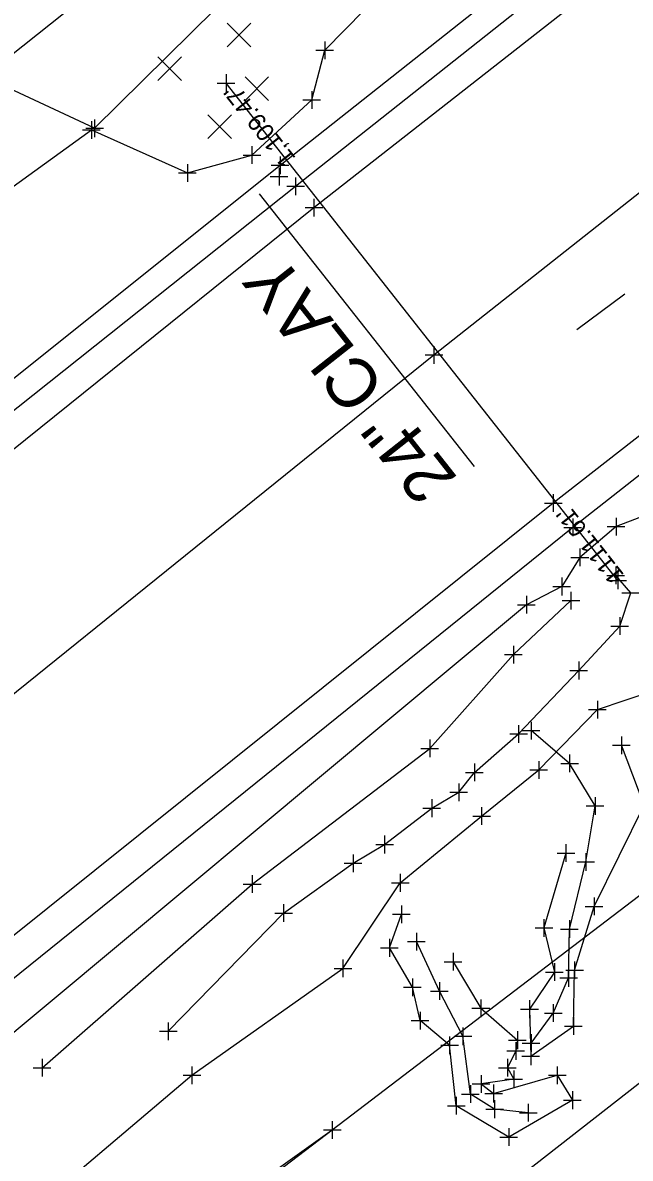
# Model space of a CAD drawing. Extents: x 2184635 to 2185378, y 369880 to 370486.
# Drawn here: x 2184841 to 2184875.3, y 370026.6 to 370090.6 of the extents above; entities that cross this region are included whole.
import ezdxf

# ---------------------------------------------------------------- set-up
doc = ezdxf.new("R2010")
doc.units = 0
for name, color, linetype in [('_CIVIL_CONSTRUCTION', 7, 'Continuous'), ('DR_X_Ditch', 7, 'Continuous'), ('DR_X_Storm_Sewer', 7, 'Continuous'), ('DR_X_Text', 7, 'Continuous'), ('GE_X_Alignment_100_Distances', 7, 'Continuous'), ('PM_X_CL_Pass_Proh_Lt', 7, 'Continuous'), ('PM_X_CL_Pass_Proh_Rt', 7, 'Continuous'), ('PM_X_Edge_Line', 7, 'Continuous'), ('PV_X_COP', 7, 'Continuous'), ('PV_X_EOP', 7, 'Continuous'), ('PV_X_Shoulder', 7, 'Continuous'), ('RD_X_Fence', 7, 'Continuous'), ('RW_X_CL', 7, 'Continuous'), ('RW_X_CL_100_Bearings', 7, 'Continuous'), ('SC_Scratch1', 7, 'Continuous'), ('SV_X_Break_Lines', 7, 'Continuous'), ('SV_X_Text', 7, 'Continuous'), ('SV_X_Top_of_Bank', 7, 'Continuous'), ('UT_X_Gas', 7, 'Continuous'), ('VG_X_Tree_Line_Lt', 7, 'Continuous')]:
    doc.layers.add(name, color=color, linetype=linetype)

msp = doc.modelspace()

# ---------------------------------------------------------------- linework, layer by layer
at = {"layer": '_CIVIL_CONSTRUCTION'}
for p, q in [((2184852.568, 370089.273), (2184853.901, 370090.608)), ((2184852.568, 370090.608), (2184853.901, 370089.273)), ((2184848.65, 370087.369), (2184849.984, 370088.704)), ((2184848.65, 370088.704), (2184849.984, 370087.369)), ((2184853.572, 370086.241), (2184854.905, 370087.576)), ((2184853.572, 370087.576), (2184854.905, 370086.241)), ((2184851.471, 370084.097), (2184852.805, 370085.432)), ((2184851.471, 370085.432), (2184852.805, 370084.097))]:
    msp.add_line(p, q, dxfattribs=at)
at = {"layer": 'DR_X_Ditch'}
msp.add_lwpolyline([(2184849.239, 370033.73), (2184855.751, 370040.4), (2184859.676, 370043.207), (2184861.454, 370044.268), (2184864.118, 370046.317), (2184865.643, 370047.216), (2184866.527, 370048.333), (2184869.021, 370050.508), (2184872.418, 370054.082), (2184874.729, 370056.587), (2184875.359, 370058.466), (2184874.504, 370059.447)], dxfattribs=at)
at = {"layer": 'DR_X_Storm_Sewer'}
msp.add_line((2184874.622, 370059.168), (2184852.499, 370087.222), dxfattribs=at)
at = {"layer": 'DR_X_Text'}
msp.add_line((2184854.367, 370080.977), (2184866.508, 370065.582), dxfattribs=at)
at = {"layer": 'GE_X_Alignment_100_Distances'}
for points in [[(2185264.317, 370371.308), (2185225.669, 370339.838), (2185186.917, 370307.744), (2185148.745, 370277.089), (2185109.073, 370245.724), (2185070.468, 370214.753), (2185031.044, 370183.419), (2184991.951, 370153.137), (2184952.243, 370122.384), (2184912.885, 370091.687), (2184876.597, 370062.99), (2184874.528, 370062.204), (2184872.479, 370060.466), (2184871.454, 370058.823), (2184869.46, 370057.791), (2184834.83, 370028.947), (2184796.151, 369998.173), (2184773.728, 369979.618), (2184757.686, 369965.832), (2184717.275, 369935.855), (2184678.357, 369904.181)], [(2184659.612, 369925.949), (2184700.373, 369957.788), (2184738.497, 369988.629), (2184777.827, 370020.252), (2184816.427, 370051.346), (2184855.546, 370082.582), (2184897.005, 370115.363), (2184935.605, 370145.229), (2184944.916, 370153.839), (2184957.869, 370164.566), (2184961.936, 370169.284), (2184974.725, 370179.722), (2184983.893, 370187.218), (2184992.505, 370194.662), (2184997.566, 370200.246)]]:
    msp.add_lwpolyline(points, dxfattribs=at)
at = {"layer": 'PM_X_CL_Pass_Proh_Lt'}
msp.add_lwpolyline([(2185262.142, 370374.202), (2185223.699, 370342.03), (2185185.178, 370310.659), (2185146.677, 370279.544), (2185107.738, 370248.35), (2185068.5, 370216.963), (2185029.051, 370186.04), (2184989.472, 370156.275), (2184949.89, 370125.369), (2184910.765, 370094.563), (2184870.979, 370063.529), (2184832.077, 370032.401), (2184793.204, 370001.486), (2184754.34, 369970.024), (2184715.121, 369938.505), (2184676.144, 369907.221)], dxfattribs=at)
at = {"layer": 'PM_X_CL_Pass_Proh_Rt'}
msp.add_lwpolyline([(2184772.075, 369998.33), (2184786.357, 370009.443), (2184824.962, 370040.257), (2184864.241, 370071.885), (2184905.968, 370104.805), (2184943.399, 370133.995), (2184983.483, 370165.213), (2185020.257, 370194.467), (2185061.224, 370226.635), (2185099.743, 370257.779), (2185139.182, 370289.511), (2185177.352, 370320.307), (2185216.054, 370351.804), (2185254.728, 370383.452)], dxfattribs=at)
at = {"layer": 'PM_X_Edge_Line'}
msp.add_lwpolyline([(2184661.525, 369922.948), (2184702.122, 369955.424), (2184740.459, 369986.306), (2184779.792, 370018.036), (2184818.421, 370048.832), (2184857.458, 370080.192), (2184899.139, 370112.801), (2184937.357, 370142.735), (2184976.78, 370173.64), (2185013.226, 370203.926), (2185054.743, 370235.213), (2185093.131, 370266.204), (2185132.902, 370298.208), (2185170.876, 370328.987), (2185209.713, 370360.437), (2185248.243, 370392.049)], dxfattribs=at)
at = {"layer": 'PV_X_COP'}
msp.add_lwpolyline([(2184667.936, 369914.544), (2184708.437, 369946.755), (2184746.444, 369977.522), (2184786.357, 370009.443), (2184824.962, 370040.257), (2184864.241, 370071.885), (2184905.968, 370104.805), (2184943.399, 370133.995), (2184983.483, 370165.213), (2185020.257, 370194.467), (2185061.224, 370226.635), (2185099.743, 370257.779), (2185139.182, 370289.511), (2185177.352, 370320.307), (2185216.054, 370351.804), (2185254.679, 370383.196)], dxfattribs=at)
at = {"layer": 'PV_X_EOP'}
for points in [[(2184661.562, 369922.858), (2184702.122, 369955.424), (2184740.459, 369986.306), (2184779.792, 370018.036), (2184818.421, 370048.832), (2184857.458, 370080.192), (2184899.139, 370112.801), (2184937.357, 370142.735), (2184976.78, 370173.64), (2185013.226, 370203.926), (2185054.743, 370235.213), (2185093.131, 370266.204), (2185132.902, 370298.208), (2185170.876, 370328.987), (2185209.713, 370360.437), (2185248.181, 370392.045)], [(2185262.152, 370374.256), (2185223.699, 370342.03), (2185185.178, 370310.659), (2185146.677, 370279.544), (2185107.738, 370248.35), (2185068.5, 370216.963), (2185029.051, 370186.04), (2184989.472, 370156.275), (2184949.89, 370125.369), (2184910.765, 370094.563), (2184870.979, 370063.529), (2184832.077, 370032.401), (2184793.204, 370001.486), (2184754.34, 369970.024), (2184715.121, 369938.505), (2184676.223, 369907.131)]]:
    msp.add_lwpolyline(points, dxfattribs=at)
at = {"layer": 'PV_X_Shoulder'}
for points in [[(2184660.616, 369924.653), (2184701.177, 369956.993), (2184739.308, 369987.689), (2184778.66, 370019.08), (2184817.145, 370050.202), (2184856.424, 370081.402), (2184897.962, 370114.276), (2184936.317, 370143.726), (2184975.811, 370174.815), (2184986.608, 370184.308), (2184994.082, 370192.548), (2185011.043, 370206.648), (2185033.171, 370224.287), (2185051.814, 370238.9), (2185062.885, 370246.964), (2185064.956, 370248.001), (2185067.328, 370248.113), (2185092.06, 370267.243), (2185132.002, 370299.513), (2185169.971, 370330.255), (2185208.837, 370361.607), (2185247.242, 370392.983)], [(2185263.127, 370373.08), (2185224.626, 370341.08), (2185185.979, 370309.587), (2185147.251, 370278.484), (2185108.316, 370247.412), (2185069.303, 370216.141), (2185029.865, 370185.151), (2184990.36, 370154.899), (2184951.083, 370123.826), (2184911.784, 370093.315), (2184872.077, 370062.156), (2184833.336, 370030.958), (2184794.18, 369999.967), (2184755.603, 369968.652), (2184716.02, 369937.324), (2184677.487, 369905.633)]]:
    msp.add_lwpolyline(points, dxfattribs=at)
at = {"layer": 'RD_X_Fence'}
for points in [[(2184709.157, 369984.536), (2184726.864, 369998.781), (2184769.898, 370032.731), (2184797.39, 370054.67), (2184814.475, 370067.872), (2184833.193, 370083.116), (2184887.166, 370125.991), (2184905.933, 370138.502)], [(2184782.754, 369936.252), (2184778.788, 369962.291), (2184805.018, 369984.824), (2184835.149, 370010.167), (2184846.096, 370019.315), (2184858.499, 370028.169), (2184882.065, 370046.135), (2184902.067, 370060.364), (2184933.298, 370086.709), (2184952.934, 370104.808), (2184969.351, 370118.703)]]:
    msp.add_lwpolyline(points, dxfattribs=at)
at = {"layer": 'RW_X_CL'}
for p, q in [((2184858.074, 370089.572), (2184858.074, 370088.572)), ((2184857.574, 370089.072), (2184858.574, 370089.072)), ((2184858.074, 370089.072), (2184858.074, 370089.072)), ((2184857.342, 370086.766), (2184857.342, 370085.766)), ((2184856.842, 370086.266), (2184857.842, 370086.266)), ((2184857.342, 370086.266), (2184857.342, 370086.266)), ((2184844.893, 370085.073), (2184844.893, 370084.073)), ((2184845.078, 370085.173), (2184845.078, 370084.173)), ((2184844.393, 370084.573), (2184845.393, 370084.573)), ((2184844.578, 370084.673), (2184845.578, 370084.673)), ((2184844.893, 370084.573), (2184844.893, 370084.573)), ((2184845.078, 370084.673), (2184845.078, 370084.673)), ((2184853.458, 370083.162), (2184854.458, 370083.162)), ((2184853.958, 370083.662), (2184853.958, 370082.662)), ((2184853.958, 370083.162), (2184853.958, 370083.162)), ((2184855.546, 370083.082), (2184855.546, 370082.082)), ((2184850.319, 370082.647), (2184850.319, 370081.647)), ((2184855.046, 370082.582), (2184856.046, 370082.582)), ((2184855.493, 370082.445), (2184855.493, 370081.445)), ((2184855.546, 370082.582), (2184855.546, 370082.582)), ((2184849.819, 370082.147), (2184850.819, 370082.147)), ((2184850.319, 370082.147), (2184850.319, 370082.147)), ((2184854.993, 370081.945), (2184855.993, 370081.945)), ((2184855.493, 370081.945), (2184855.493, 370081.945)), ((2184856.424, 370081.902), (2184856.424, 370080.902)), ((2184855.924, 370081.402), (2184856.924, 370081.402)), ((2184856.424, 370081.402), (2184856.424, 370081.402)), ((2184857.458, 370080.692), (2184857.458, 370079.692)), ((2184857.458, 370080.692), (2184857.458, 370079.692)), ((2184856.958, 370080.192), (2184857.958, 370080.192)), ((2184856.958, 370080.192), (2184857.958, 370080.192)), ((2184857.458, 370080.192), (2184857.458, 370080.192)), ((2184857.458, 370080.192), (2184857.458, 370080.192)), ((2184864.241, 370072.385), (2184864.241, 370071.385)), ((2184864.241, 370072.385), (2184864.241, 370071.385)), ((2184863.741, 370071.885), (2184864.741, 370071.885)), ((2184863.741, 370071.885), (2184864.741, 370071.885)), ((2184864.241, 370071.885), (2184864.241, 370071.885)), ((2184864.241, 370071.885), (2184864.241, 370071.885)), ((2184870.979, 370064.029), (2184870.979, 370063.029)), ((2184870.979, 370064.029), (2184870.979, 370063.029)), ((2184870.479, 370063.529), (2184871.479, 370063.529)), ((2184870.479, 370063.529), (2184871.479, 370063.529)), ((2184870.979, 370063.529), (2184870.979, 370063.529)), ((2184870.979, 370063.529), (2184870.979, 370063.529)), ((2184872.077, 370062.656), (2184872.077, 370061.656)), ((2184874.528, 370062.704), (2184874.528, 370061.704)), ((2184871.577, 370062.156), (2184872.577, 370062.156)), ((2184872.077, 370062.156), (2184872.077, 370062.156)), ((2184874.028, 370062.204), (2184875.028, 370062.204)), ((2184874.528, 370062.204), (2184874.528, 370062.204)), ((2184872.479, 370060.966), (2184872.479, 370059.966)), ((2184871.979, 370060.466), (2184872.979, 370060.466)), ((2184872.479, 370060.466), (2184872.479, 370060.466)), ((2184874.004, 370059.447), (2184875.004, 370059.447)), ((2184874.504, 370059.947), (2184874.504, 370058.947)), ((2184874.504, 370059.447), (2184874.504, 370059.447)), ((2184870.954, 370058.823), (2184871.954, 370058.823)), ((2184871.454, 370059.323), (2184871.454, 370058.323)), ((2184871.454, 370058.823), (2184871.454, 370058.823)), ((2184869.46, 370058.291), (2184869.46, 370057.291)), ((2184871.978, 370058.524), (2184871.978, 370057.524)), ((2184874.859, 370058.466), (2184875.859, 370058.466)), ((2184868.96, 370057.791), (2184869.96, 370057.791)), ((2184869.46, 370057.791), (2184869.46, 370057.791)), ((2184871.478, 370058.024), (2184872.478, 370058.024)), ((2184871.978, 370058.024), (2184871.978, 370058.024)), ((2184874.729, 370057.087), (2184874.729, 370056.087)), ((2184874.229, 370056.587), (2184875.229, 370056.587)), ((2184874.729, 370056.587), (2184874.729, 370056.587)), ((2184868.23, 370054.977), (2184869.23, 370054.977)), ((2184868.73, 370055.477), (2184868.73, 370054.477)), ((2184868.73, 370054.977), (2184868.73, 370054.977)), ((2184872.418, 370054.582), (2184872.418, 370053.582)), ((2184871.918, 370054.082), (2184872.918, 370054.082)), ((2184872.418, 370054.082), (2184872.418, 370054.082)), ((2184873.468, 370052.374), (2184873.468, 370051.374)), ((2184872.968, 370051.874), (2184873.968, 370051.874)), ((2184873.468, 370051.874), (2184873.468, 370051.874)), ((2184869.726, 370051.192), (2184869.726, 370050.192)), ((2184868.521, 370050.508), (2184869.521, 370050.508)), ((2184869.021, 370051.008), (2184869.021, 370050.008)), ((2184869.021, 370050.508), (2184869.021, 370050.508)), ((2184869.226, 370050.692), (2184870.226, 370050.692)), ((2184869.726, 370050.692), (2184869.726, 370050.692)), ((2184864.005, 370050.188), (2184864.005, 370049.188)), ((2184874.326, 370049.868), (2184875.326, 370049.868)), ((2184874.826, 370050.368), (2184874.826, 370049.368)), ((2184874.826, 370049.868), (2184874.826, 370049.868)), ((2184863.505, 370049.688), (2184864.505, 370049.688)), ((2184864.005, 370049.688), (2184864.005, 370049.688)), ((2184871.899, 370049.346), (2184871.899, 370048.346)), ((2184866.527, 370048.833), (2184866.527, 370047.833)), ((2184870.157, 370048.973), (2184870.157, 370047.973)), ((2184871.399, 370048.846), (2184872.399, 370048.846)), ((2184871.899, 370048.846), (2184871.899, 370048.846)), ((2184866.027, 370048.333), (2184867.027, 370048.333)), ((2184866.527, 370048.333), (2184866.527, 370048.333)), ((2184869.657, 370048.473), (2184870.657, 370048.473)), ((2184870.157, 370048.473), (2184870.157, 370048.473)), ((2184865.143, 370047.216), (2184866.143, 370047.216)), ((2184865.643, 370047.716), (2184865.643, 370046.716)), ((2184865.643, 370047.216), (2184865.643, 370047.216)), ((2184864.118, 370046.817), (2184864.118, 370045.817)), ((2184873.342, 370046.947), (2184873.342, 370045.947)), ((2184863.618, 370046.317), (2184864.618, 370046.317)), ((2184864.118, 370046.317), (2184864.118, 370046.317)), ((2184866.927, 370046.369), (2184866.927, 370045.369)), ((2184872.842, 370046.447), (2184873.842, 370046.447)), ((2184873.342, 370046.447), (2184873.342, 370046.447)), ((2184866.427, 370045.869), (2184867.427, 370045.869)), ((2184866.927, 370045.869), (2184866.927, 370045.869)), ((2184861.454, 370044.768), (2184861.454, 370043.768)), ((2184860.954, 370044.268), (2184861.954, 370044.268)), ((2184861.454, 370044.268), (2184861.454, 370044.268)), ((2184871.692, 370044.282), (2184871.692, 370043.282)), ((2184859.676, 370043.707), (2184859.676, 370042.707)), ((2184871.192, 370043.782), (2184872.192, 370043.782)), ((2184871.692, 370043.782), (2184871.692, 370043.782)), ((2184872.811, 370043.782), (2184872.811, 370042.782)), ((2184859.176, 370043.207), (2184860.176, 370043.207)), ((2184859.676, 370043.207), (2184859.676, 370043.207)), ((2184872.311, 370043.282), (2184873.311, 370043.282)), ((2184872.811, 370043.282), (2184872.811, 370043.282)), ((2184853.975, 370042.539), (2184853.975, 370041.539)), ((2184861.834, 370042.107), (2184862.834, 370042.107)), ((2184862.334, 370042.607), (2184862.334, 370041.607)), ((2184862.334, 370042.107), (2184862.334, 370042.107)), ((2184853.475, 370042.039), (2184854.475, 370042.039)), ((2184853.975, 370042.039), (2184853.975, 370042.039)), ((2184855.751, 370040.9), (2184855.751, 370039.9)), ((2184862.398, 370040.832), (2184862.398, 370039.832)), ((2184873.282, 370041.277), (2184873.282, 370040.277)), ((2184855.251, 370040.4), (2184856.251, 370040.4)), ((2184855.751, 370040.4), (2184855.751, 370040.4)), ((2184861.898, 370040.332), (2184862.898, 370040.332)), ((2184862.398, 370040.332), (2184862.398, 370040.332)), ((2184872.782, 370040.777), (2184873.782, 370040.777)), ((2184873.282, 370040.777), (2184873.282, 370040.777)), ((2184869.952, 370039.558), (2184870.952, 370039.558)), ((2184870.452, 370040.058), (2184870.452, 370039.058)), ((2184870.452, 370039.558), (2184870.452, 370039.558)), ((2184871.89, 370039.998), (2184871.89, 370038.998)), ((2184861.725, 370038.94), (2184861.725, 370037.94)), ((2184863.249, 370039.29), (2184863.249, 370038.29)), ((2184871.39, 370039.498), (2184872.39, 370039.498)), ((2184871.89, 370039.498), (2184871.89, 370039.498)), ((2184861.225, 370038.44), (2184862.225, 370038.44)), ((2184861.725, 370038.44), (2184861.725, 370038.44)), ((2184862.749, 370038.79), (2184863.749, 370038.79)), ((2184863.249, 370038.79), (2184863.249, 370038.79)), ((2184859.1, 370037.781), (2184859.1, 370036.781)), ((2184864.822, 370037.654), (2184865.822, 370037.654)), ((2184865.322, 370038.154), (2184865.322, 370037.154)), ((2184865.322, 370037.654), (2184865.322, 370037.654)), ((2184872.18, 370037.677), (2184872.18, 370036.677)), ((2184858.6, 370037.281), (2184859.6, 370037.281)), ((2184859.1, 370037.281), (2184859.1, 370037.281)), ((2184870.544, 370037.074), (2184871.544, 370037.074)), ((2184871.044, 370037.574), (2184871.044, 370036.574)), ((2184871.044, 370037.074), (2184871.044, 370037.074)), ((2184871.68, 370037.177), (2184872.68, 370037.177)), ((2184871.842, 370037.242), (2184871.842, 370036.242)), ((2184872.18, 370037.177), (2184872.18, 370037.177)), ((2184863.023, 370036.713), (2184863.023, 370035.713)), ((2184864.544, 370036.501), (2184864.544, 370035.501)), ((2184871.342, 370036.742), (2184872.342, 370036.742)), ((2184871.842, 370036.742), (2184871.842, 370036.742)), ((2184862.523, 370036.213), (2184863.523, 370036.213)), ((2184863.023, 370036.213), (2184863.023, 370036.213)), ((2184864.044, 370036.001), (2184865.044, 370036.001)), ((2184864.544, 370036.001), (2184864.544, 370036.001)), ((2184866.387, 370035.032), (2184867.387, 370035.032)), ((2184866.887, 370035.532), (2184866.887, 370034.532)), ((2184866.887, 370035.032), (2184866.887, 370035.032)), ((2184869.637, 370035.48), (2184869.637, 370034.48)), ((2184870.975, 370035.258), (2184870.975, 370034.258)), ((2184863.459, 370034.831), (2184863.459, 370033.831)), ((2184869.137, 370034.98), (2184870.137, 370034.98)), ((2184869.637, 370034.98), (2184869.637, 370034.98)), ((2184870.475, 370034.758), (2184871.475, 370034.758)), ((2184870.975, 370034.758), (2184870.975, 370034.758)), ((2184872.117, 370034.528), (2184872.117, 370033.528)), ((2184849.239, 370034.23), (2184849.239, 370033.23)), ((2184862.959, 370034.331), (2184863.959, 370034.331)), ((2184863.459, 370034.331), (2184863.459, 370034.331)), ((2184865.875, 370033.952), (2184865.875, 370032.952)), ((2184871.617, 370034.028), (2184872.617, 370034.028)), ((2184872.117, 370034.028), (2184872.117, 370034.028)), ((2184848.739, 370033.73), (2184849.739, 370033.73)), ((2184849.239, 370033.73), (2184849.239, 370033.73)), ((2184865.126, 370033.441), (2184865.126, 370032.441)), ((2184865.375, 370033.452), (2184866.375, 370033.452)), ((2184865.875, 370033.452), (2184865.875, 370033.452)), ((2184868.45, 370033.231), (2184869.45, 370033.231)), ((2184868.859, 370033.122), (2184868.859, 370032.122)), ((2184868.95, 370033.731), (2184868.95, 370032.731)), ((2184868.95, 370033.231), (2184868.95, 370033.231)), ((2184869.722, 370033.564), (2184869.722, 370032.564)), ((2184864.626, 370032.941), (2184865.626, 370032.941)), ((2184865.126, 370032.941), (2184865.126, 370032.941)), ((2184868.359, 370032.622), (2184869.359, 370032.622)), ((2184868.859, 370032.622), (2184868.859, 370032.622)), ((2184869.222, 370033.064), (2184870.222, 370033.064)), ((2184869.704, 370032.82), (2184869.704, 370031.82)), ((2184869.722, 370033.064), (2184869.722, 370033.064)), ((2184842.106, 370032.179), (2184842.106, 370031.179)), ((2184868.386, 370032.177), (2184868.386, 370031.177)), ((2184869.204, 370032.32), (2184870.204, 370032.32)), ((2184869.704, 370032.32), (2184869.704, 370032.32)), ((2184841.606, 370031.679), (2184842.606, 370031.679)), ((2184842.106, 370031.679), (2184842.106, 370031.679)), ((2184850.07, 370031.252), (2184851.07, 370031.252)), ((2184850.57, 370031.752), (2184850.57, 370030.752)), ((2184850.57, 370031.252), (2184850.57, 370031.252)), ((2184866.898, 370031.261), (2184866.898, 370030.261)), ((2184867.886, 370031.677), (2184868.886, 370031.677)), ((2184868.386, 370031.677), (2184868.386, 370031.677)), ((2184868.742, 370031.522), (2184868.742, 370030.522)), ((2184870.706, 370031.253), (2184871.706, 370031.253)), ((2184871.206, 370031.753), (2184871.206, 370030.753)), ((2184871.206, 370031.253), (2184871.206, 370031.253)), ((2184866.302, 370030.693), (2184866.302, 370029.693)), ((2184866.398, 370030.761), (2184867.398, 370030.761)), ((2184866.898, 370030.761), (2184866.898, 370030.761)), ((2184867.609, 370030.721), (2184867.609, 370029.721)), ((2184868.242, 370031.022), (2184869.242, 370031.022)), ((2184868.742, 370031.022), (2184868.742, 370031.022)), ((2184865.497, 370030.035), (2184865.497, 370029.035)), ((2184865.802, 370030.193), (2184866.802, 370030.193)), ((2184866.302, 370030.193), (2184866.302, 370030.193)), ((2184867.109, 370030.221), (2184868.109, 370030.221)), ((2184867.609, 370030.221), (2184867.609, 370030.221)), ((2184872.063, 370030.346), (2184872.063, 370029.346)), ((2184864.997, 370029.535), (2184865.997, 370029.535)), ((2184865.497, 370029.535), (2184865.497, 370029.535)), ((2184867.167, 370029.338), (2184868.167, 370029.338)), ((2184867.667, 370029.838), (2184867.667, 370028.838)), ((2184867.667, 370029.338), (2184867.667, 370029.338)), ((2184869.57, 370029.637), (2184869.57, 370028.637)), ((2184871.563, 370029.846), (2184872.563, 370029.846)), ((2184872.063, 370029.846), (2184872.063, 370029.846)), ((2184858.499, 370028.669), (2184858.499, 370027.669)), ((2184858.499, 370028.669), (2184858.499, 370027.669)), ((2184869.07, 370029.137), (2184870.07, 370029.137)), ((2184869.57, 370029.137), (2184869.57, 370029.137)), ((2184857.999, 370028.169), (2184858.999, 370028.169)), ((2184857.999, 370028.169), (2184858.999, 370028.169)), ((2184858.499, 370028.169), (2184858.499, 370028.169)), ((2184858.499, 370028.169), (2184858.499, 370028.169)), ((2184868.461, 370028.266), (2184868.461, 370027.266)), ((2184867.961, 370027.766), (2184868.961, 370027.766)), ((2184868.461, 370027.766), (2184868.461, 370027.766))]:
    msp.add_line(p, q, dxfattribs=at)
at = {"layer": 'RW_X_CL_100_Bearings'}
for p, q in [((2184852.499, 370087.722), (2184852.499, 370086.722)), ((2184851.999, 370087.222), (2184852.999, 370087.222)), ((2184852.499, 370087.222), (2184852.499, 370087.222)), ((2184874.622, 370059.668), (2184874.622, 370058.668)), ((2184874.122, 370059.168), (2184875.122, 370059.168)), ((2184874.622, 370059.168), (2184874.622, 370059.168))]:
    msp.add_line(p, q, dxfattribs=at)
at = {"layer": 'SV_X_Break_Lines'}
for points in [[(2184842.106, 370031.679), (2184853.975, 370042.039), (2184864.005, 370049.688), (2184868.73, 370054.977), (2184871.978, 370058.024)], [(2184773.099, 369972.331), (2184782.4, 369979.42), (2184789.638, 369983.788), (2184799.975, 369993.188), (2184809.134, 369999.332), (2184821.188, 370007.547), (2184840.048, 370022.345), (2184850.57, 370031.252), (2184859.1, 370037.281), (2184862.334, 370042.107), (2184866.927, 370045.869), (2184870.157, 370048.473), (2184873.468, 370051.874), (2184876.592, 370052.942), (2184880.004, 370051.775), (2184881.445, 370049.54), (2184882.459, 370048.357)], [(2184869.722, 370033.064), (2184870.975, 370034.758), (2184871.842, 370036.742), (2184871.89, 370039.498), (2184872.811, 370043.282), (2184873.342, 370046.447), (2184871.899, 370048.846), (2184869.726, 370050.692)], [(2184871.692, 370043.782), (2184870.452, 370039.558), (2184871.044, 370037.074), (2184869.637, 370034.98), (2184869.704, 370032.32), (2184872.117, 370034.028), (2184872.18, 370037.177), (2184873.282, 370040.777), (2184876.119, 370046.488), (2184874.826, 370049.868)], [(2184865.322, 370037.654), (2184866.887, 370035.032), (2184868.95, 370033.231), (2184868.859, 370032.622), (2184868.386, 370031.677), (2184868.742, 370031.022), (2184866.898, 370030.761), (2184867.609, 370030.221), (2184871.206, 370031.253), (2184872.063, 370029.846), (2184868.461, 370027.766), (2184865.497, 370029.535), (2184865.126, 370032.941), (2184863.459, 370034.331), (2184863.023, 370036.213), (2184861.725, 370038.44), (2184862.398, 370040.332)], [(2184869.57, 370029.137), (2184867.667, 370029.338), (2184866.302, 370030.193), (2184865.875, 370033.452), (2184864.544, 370036.001), (2184863.249, 370038.79)]]:
    msp.add_lwpolyline(points, dxfattribs=at)
at = {"layer": 'SV_X_Text'}
msp.add_line((2184872.318, 370073.316), (2184875.023, 370075.331), dxfattribs=at)
at = {"layer": 'SV_X_Top_of_Bank'}
for points in [[(2184834.448, 370083.78), (2184836.257, 370081.529), (2184839.923, 370080.988), (2184844.893, 370084.573), (2184850.319, 370082.147), (2184853.958, 370083.162), (2184857.342, 370086.266), (2184858.074, 370089.072), (2184861.427, 370092.497), (2184863.541, 370097.423), (2184865.421, 370100.214), (2184872.27, 370099.955), (2184876.425, 370103.916), (2184881.307, 370108.241), (2184882.469, 370112.922), (2184883.938, 370117.722), (2184887.117, 370120.048)], [(2184783.25, 369936.356), (2184778.788, 369962.291), (2184778.747, 369967.97), (2184803.46, 369987.128), (2184831.56, 370007.676), (2184858.499, 370028.169)]]:
    msp.add_lwpolyline(points, dxfattribs=at)
at = {"layer": 'UT_X_Gas'}
msp.add_lwpolyline([(2184699.867, 369890.142), (2184718.364, 369905.922), (2184745.493, 369924.984), (2184756.714, 369934.518), (2184762.36, 369938.036), (2184795.231, 369963.996), (2184842.055, 370004.454), (2184886.231, 370038.937), (2184899.072, 370046.885), (2184918.449, 370060.147), (2184933.569, 370078.059), (2184948.534, 370093.678)], dxfattribs=at)
at = {"layer": 'VG_X_Tree_Line_Lt'}
msp.add_lwpolyline([(2185010.677, 370261.152), (2185009.496, 370230.83), (2184994.447, 370214.873), (2184919.447, 370148.63), (2184883.31, 370122.364), (2184845.078, 370084.673), (2184789.476, 370110.598), (2184762.675, 370135.815)], dxfattribs=at)

# ---------------------------------------------------------------- texts
at = {"layer": 'DR_X_Text'}
msp.add_text('24" CLAY', height=2.8, rotation=128.25863, dxfattribs=at).set_placement((2184865.618, 370064.932))
at = {"layer": 'SC_Scratch1'}
for s, p in [("1,109.47'", (2184856.472, 370082.992)), ("1111.61'", (2184875.015, 370059.478))]:
    msp.add_text(s, height=1, rotation=128.25863, dxfattribs=at).set_placement(p)

doc.saveas('drawing.dxf')
